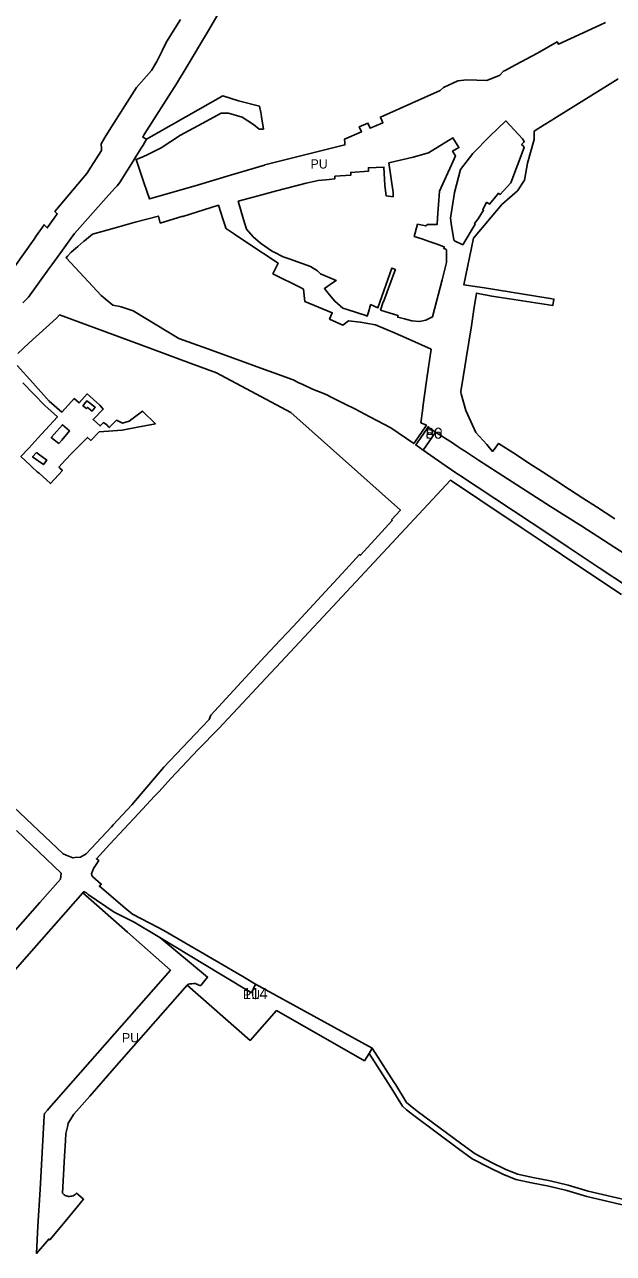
# Model space of a CAD drawing. Extents: x -537034 to -534353, y -1176562 to -1173176.
# Drawn here: x -536157 to -535838, y -1175930 to -1175264 of the extents above; entities that cross this region are included whole.
import ezdxf

# ---------------------------------------------------------------- set-up
doc = ezdxf.new("R2010")
doc.units = 0
for name, color, linetype in [('90320013', 7, 'Continuous'), ('90320023', 7, 'Continuous'), ('90450013', 7, 'Continuous'), ('90450023', 7, 'Continuous'), ('ID_navrh', 7, 'Continuous')]:
    doc.layers.add(name, color=color, linetype=linetype)

msp = doc.modelspace()

# ---------------------------------------------------------------- linework, layer by layer
at = {"layer": '90320013'}
for points in [[(-536006.58, -1175180), (-536057.72, -1175267.69), (-536069.4, -1175287.13), (-536074.57, -1175295.75), (-536092.07, -1175323.29), (-536092.88, -1175324.61), (-536090.76, -1175325.85), (-536092.69, -1175328.97), (-536093.75, -1175330.67), (-536096.43, -1175335), (-536098.11, -1175337.72), (-536104.15, -1175347.45), (-536105.27, -1175349.25), (-536106.82, -1175350.99), (-536107.99, -1175352.3), (-536112.75, -1175357.64), (-536129.84, -1175376.84), (-536131.8, -1175379.55), (-536136.42, -1175385.95), (-536142.22, -1175393.97), (-536143.72, -1175396.05), (-536154.83, -1175411.41), (-536157.86, -1175414.59)], [(-536162.37, -1175394.92), (-536151.81, -1175379.91), (-536150.51, -1175378.06), (-536146.37, -1175372.18), (-536144.69, -1175373.91), (-536144.13, -1175373.13), (-536142.38, -1175370.67), (-536140.9, -1175368.58), (-536139.22, -1175366.23), (-536140.48, -1175364.96), (-536133.87, -1175357.08), (-536125.22, -1175346.76), (-536123.14, -1175344.33), (-536120.96, -1175340.95), (-536115.18, -1175331.96), (-536115.24, -1175330.93), (-536115.4, -1175328.29), (-536113.39, -1175324.91), (-536111.06, -1175320.99), (-536096.32, -1175297.69), (-536088.03, -1175288.6), (-536085.27, -1175283.61), (-536082.34, -1175277.81), (-536079.94, -1175273.05), (-536072.44, -1175260.84)]]:
    msp.add_lwpolyline(points, dxfattribs=at)
at = {"layer": '90320023'}
msp.add_lwpolyline([(-535831.2, -1175903.92), (-535852.06, -1175898.92), (-535862.82, -1175895.79), (-535872.59, -1175893.44), (-535881.94, -1175891.57), (-535890.48, -1175889.76), (-535897.59, -1175886.87), (-535904.65, -1175883.37), (-535914.14, -1175878.49), (-535921.6, -1175873.09), (-535945.82, -1175855.15), (-535949.79, -1175851.94), (-535952.05, -1175849.98), (-535958.16, -1175840.1), (-535958.19, -1175840.06), (-535970.14, -1175821.39), (-535968.39, -1175818.56), (-535956.44, -1175837.23), (-535955.62, -1175838.5), (-535949.74, -1175848.02), (-535947.86, -1175849.64), (-535943.98, -1175852.77), (-535919.82, -1175870.67), (-535912.56, -1175875.93), (-535903.3, -1175880.69), (-535896.35, -1175884.13), (-535889.59, -1175886.88), (-535881.33, -1175888.64), (-535871.94, -1175890.51), (-535862.05, -1175892.89), (-535851.29, -1175896.02), (-535830.38, -1175901.03)], dxfattribs=at)
at = {"layer": '90450013'}
for points in [[(-536157.86, -1175414.59), (-536154.83, -1175411.41), (-536143.72, -1175396.05), (-536142.22, -1175393.97), (-536136.42, -1175385.95), (-536131.8, -1175379.55), (-536129.84, -1175376.84), (-536112.75, -1175357.64), (-536107.99, -1175352.3), (-536106.82, -1175350.99), (-536105.27, -1175349.25), (-536104.15, -1175347.45), (-536098.11, -1175337.72), (-536096.43, -1175335), (-536093.75, -1175330.67), (-536092.69, -1175328.97), (-536090.76, -1175325.85), (-536056.18, -1175306.04), (-536049.5, -1175302.21), (-536040.85, -1175304.92), (-536029.59, -1175307.87), (-536028.73, -1175311.35), (-536028.63, -1175312.06), (-536028.39, -1175313.76), (-536027.63, -1175319.02), (-536027.44, -1175320.35), (-536029.77, -1175320.33), (-536032.73, -1175317.76), (-536038.85, -1175313.85), (-536046.36, -1175311.63), (-536050.36, -1175311.71), (-536060.56, -1175317.19), (-536072.32, -1175323.69), (-536082.9, -1175330.42), (-536089.72, -1175333.91), (-536093.25, -1175335.47), (-536096.47, -1175336.83), (-536092.3, -1175349.19), (-536090.67, -1175354.01), (-536089.26, -1175358.2), (-536075.74, -1175354.33), (-536062.61, -1175350.5), (-536045.32, -1175345.23), (-536026.8, -1175339.78), (-536026.63, -1175339.73), (-535983.2, -1175328.86), (-535983.27, -1175327.65), (-535983.37, -1175325.73), (-535974.27, -1175321.85), (-535975.41, -1175319.17), (-535970.74, -1175317.01), (-535969.56, -1175319.81), (-535962.64, -1175316.84), (-535963.93, -1175313.84), (-535962.27, -1175313.07), (-535931.61, -1175299.47), (-535929.82, -1175297.79), (-535921.95, -1175294.08), (-535917.14, -1175293.69), (-535906.3, -1175294.03), (-535899.54, -1175291.17), (-535899.11, -1175290.99), (-535897.13, -1175288.99), (-535896.37, -1175288.59), (-535890.61, -1175285.56), (-535878.76, -1175279.15), (-535868.04, -1175273.09), (-535867.34, -1175274.28), (-535854.08, -1175268.05), (-535845.03, -1175263.95), (-535841.93, -1175262.54)], [(-535834.99, -1175293.05), (-535839.37, -1175295.79), (-535851.34, -1175303.26), (-535869.92, -1175314.78), (-535870.92, -1175315.4), (-535875.07, -1175317.97), (-535880.62, -1175321.52), (-535880.5, -1175326.03), (-535884.23, -1175338.72), (-535885.84, -1175347.99), (-535889.55, -1175353.76), (-535898.06, -1175361.28), (-535913.48, -1175379.39), (-535918.79, -1175404.67), (-535911.3, -1175405.81), (-535907.6, -1175406.38), (-535871.88, -1175412.1), (-535869.83, -1175412.49), (-535870.37, -1175415.86), (-535893.97, -1175412.4), (-535903.47, -1175410.92), (-535911.79, -1175409.25), (-535913.21, -1175418.12), (-535914.63, -1175427), (-535916.04, -1175435.87), (-535917.46, -1175444.75), (-535918.88, -1175453.63), (-535920.3, -1175462.5), (-535920.4, -1175463.19), (-535920.21, -1175463.87), (-535917.69, -1175472.82), (-535912.13, -1175484.72), (-535906.33, -1175491.38), (-535903.16, -1175495.01), (-535902.34, -1175493.94), (-535899.85, -1175490.69), (-535890.72, -1175496.62), (-535883.39, -1175501.37), (-535876.07, -1175506.12), (-535868.76, -1175510.86), (-535861.43, -1175515.62), (-535854.11, -1175520.37), (-535846.78, -1175525.12), (-535836.82, -1175531.58)], [(-536166.27, -1175684.73), (-536135.96, -1175713.3), (-536134.39, -1175713.94), (-536130.78, -1175715.4), (-536129.64, -1175715.27), (-536126.67, -1175714.93), (-536123.54, -1175713.17), (-536109.87, -1175698.52), (-536108.98, -1175697.57), (-536098.8, -1175686.65), (-536090.64, -1175677.08), (-536089.6, -1175675.86), (-536081.43, -1175666.28), (-536064.41, -1175648.4), (-536056.8, -1175640.41), (-536056.02, -1175638.08), (-536039.26, -1175619.95), (-536026.58, -1175606.23), (-536018.16, -1175597.18), (-536011.37, -1175589.88), (-535982.79, -1175559.15), (-535975.24, -1175550.95), (-535974.85, -1175551.32), (-535957.51, -1175532.51), (-535957.92, -1175532.13), (-535953.14, -1175526.94), (-536012.46, -1175474), (-536052.95, -1175452.48), (-536067.19, -1175447.21), (-536093.87, -1175437.34), (-536137.96, -1175421.02), (-536139.69, -1175422.77), (-536154.62, -1175436.42), (-536160.63, -1175442.04)], [(-536161.02, -1175448.4), (-536152.52, -1175457.9), (-536143.69, -1175467.75), (-536136.82, -1175473.77), (-536131.49, -1175467.97), (-536130.05, -1175466.4), (-536127.41, -1175468.77), (-536122.94, -1175463.84), (-536116.13, -1175469.96), (-536114.25, -1175472.08), (-536119.83, -1175477.7), (-536116.04, -1175481.25), (-536114.16, -1175479.39), (-536112.4, -1175480.71), (-536111.06, -1175482.13), (-536107.55, -1175478.6), (-536107.11, -1175478.16), (-536103.78, -1175479.67), (-536100.16, -1175478.69), (-536093.04, -1175473.16), (-536086.02, -1175480.07), (-536095.7, -1175481.89), (-536104.07, -1175483.46), (-536116.44, -1175484.37), (-536121.1, -1175489.13), (-536122.87, -1175487.43), (-536128.23, -1175492.92), (-536131.48, -1175496.25), (-536134.83, -1175499.68), (-536138.31, -1175503.67), (-536137.84, -1175504.11), (-536136.45, -1175505.41), (-536142.92, -1175512.53), (-536149.09, -1175506.89), (-536150.04, -1175506.03), (-536152.96, -1175503.36), (-536153.95, -1175502.45), (-536158.95, -1175497.88), (-536154.68, -1175493.22), (-536149.75, -1175487.86), (-536145.64, -1175483.38), (-536139.11, -1175476.27), (-536145.9, -1175470.18), (-536157.81, -1175457.83)], [(-535828.09, -1175552.76), (-535854.81, -1175535.62), (-535871.63, -1175524.85), (-535879.25, -1175519.97), (-535910.82, -1175499.75), (-535912.86, -1175498.4), (-535918.33, -1175494.77), (-535919.58, -1175493.94), (-535922.29, -1175492.15), (-535924.91, -1175490.41), (-535934.02, -1175484.62), (-535937.94, -1175482.12), (-535937.87, -1175481.61), (-535940.62, -1175485.52), (-535942.28, -1175487.89), (-535944.84, -1175491.52), (-535940.73, -1175494.38), (-535930.72, -1175501.34), (-535922.97, -1175506.73), (-535922.56, -1175507.02), (-535921.1, -1175507.99), (-535872.67, -1175539.97), (-535862.15, -1175546.92), (-535845.34, -1175558.14), (-535830.04, -1175568.35)], [(-535833.24, -1175572.63), (-535847.63, -1175563), (-535865.17, -1175551.3), (-535875.69, -1175544.28), (-535887.07, -1175536.66), (-535910.06, -1175521.32), (-535924.9, -1175511.41), (-535925.98, -1175510.69), (-535977.32, -1175565.72), (-536020.48, -1175611.98), (-536020.82, -1175612.35), (-536051.58, -1175645.22), (-536062.85, -1175656.58), (-536077.69, -1175672.45), (-536084.04, -1175679.34), (-536086.5, -1175681.99), (-536095.14, -1175691.31), (-536110.68, -1175708), (-536117.97, -1175715.86), (-536116.69, -1175716.89), (-536117.43, -1175717.85), (-536119.59, -1175721.2), (-536120.66, -1175723.99), (-536120.53, -1175724.95), (-536119.96, -1175725.77), (-536115.4, -1175729.64), (-536116.38, -1175730.76), (-536102.6, -1175742.46), (-536098.47, -1175745.97), (-536084.46, -1175753.22), (-536081.42, -1175754.71), (-536047.3, -1175774.7), (-536044.2, -1175776.52), (-536038.6, -1175779.8), (-536031.75, -1175783.82), (-536033.88, -1175788.53), (-536050.74, -1175778.38), (-536083.6, -1175758.57), (-536097.58, -1175750.2), (-536108.31, -1175744.92), (-536122.41, -1175735.27), (-536123.44, -1175734.4), (-536124.31, -1175733.91), (-536124.75, -1175733.67), (-536125.34, -1175734.39), (-536138.55, -1175749.41), (-536151.76, -1175764.43), (-536164.97, -1175779.44)], [(-536161.83, -1175754.68), (-536148.62, -1175739.66), (-536137.41, -1175726.91), (-536137.07, -1175723.72), (-536161.26, -1175700.56)]]:
    msp.add_lwpolyline(points, dxfattribs=at)
for points in [[(-535906.34, -1175359.86), (-535904.88, -1175361.02), (-535901.28, -1175356.77), (-535899.88, -1175355.12), (-535899.09, -1175355.7), (-535897.43, -1175353.97), (-535893.14, -1175349.5), (-535886.06, -1175330.37), (-535886.56, -1175329.45), (-535887.38, -1175328.59), (-535886.24, -1175327.4), (-535885.94, -1175327.08), (-535886.86, -1175325.6), (-535895.9, -1175315.86), (-535904.64, -1175324.13), (-535913.78, -1175333.54), (-535920.54, -1175342.19), (-535923.85, -1175354.67), (-535925.89, -1175368.6), (-535925.38, -1175372.73), (-535924.2, -1175380.17), (-535924.08, -1175380.55), (-535923.75, -1175380.8), (-535919.27, -1175382.97), (-535912.63, -1175371.84), (-535912.86, -1175371.55), (-535911.01, -1175368.92), (-535908.05, -1175364.29), (-535908.49, -1175364)], [(-536033.03, -1175378.74), (-536029.05, -1175382.09), (-536022.5, -1175386.59), (-536021.61, -1175387.05), (-536016.68, -1175389.63), (-536013.48, -1175390.72), (-536001.83, -1175394.83), (-535998.08, -1175397.19), (-535996.48, -1175398.8), (-535987.93, -1175402.35), (-535989.36, -1175403.33), (-535994.33, -1175406.75), (-535992.24, -1175409.31), (-535991.58, -1175410.12), (-535988.7, -1175413.65), (-535984.32, -1175417.42), (-535981.97, -1175418.18), (-535971.92, -1175421.43), (-535971.07, -1175421.71), (-535970.47, -1175419.62), (-535969.54, -1175416.37), (-535969.28, -1175415.49), (-535965.34, -1175417.27), (-535957.76, -1175395.69), (-535955.8, -1175396.5), (-535956.39, -1175397.77), (-535962.34, -1175414.02), (-535962.47, -1175413.98), (-535963.89, -1175418.41), (-535954.48, -1175421.34), (-535954.59, -1175422.36), (-535950.86, -1175423.25), (-535946.91, -1175424.19), (-535942.68, -1175424.63), (-535939.3, -1175423.93), (-535935.67, -1175422.14), (-535930.51, -1175402.01), (-535928.04, -1175392.62), (-535928.17, -1175385.78), (-535928.46, -1175385.39), (-535929.65, -1175384.98), (-535929.35, -1175384.08), (-535933.8, -1175382.49), (-535937.52, -1175381.22), (-535941.5, -1175379.86), (-535945.61, -1175378.45), (-535943.8, -1175371.87), (-535939.34, -1175372.83), (-535938.43, -1175371.97), (-535933.11, -1175371.95), (-535933.01, -1175368.46), (-535931.93, -1175354.02), (-535928.3, -1175345.93), (-535925.36, -1175339.68), (-535923.29, -1175334.88), (-535924.78, -1175332.21), (-535921.41, -1175330.35), (-535924.67, -1175325.13), (-535937.9, -1175333.24), (-535946.12, -1175335.5), (-535959.32, -1175338.64), (-535957.04, -1175354.74), (-535957.09, -1175357), (-535960.79, -1175356.57), (-535961.56, -1175350.82), (-535962.06, -1175340.94), (-535970.46, -1175341.25), (-535970.35, -1175343.05), (-535980.06, -1175343.81), (-535980.04, -1175345.3), (-535988.67, -1175345.91), (-535988.6, -1175347.22), (-535991.84, -1175347.55), (-535997.66, -1175348.18), (-536004.2, -1175349.6), (-536020.27, -1175353.73), (-536032.27, -1175357.01), (-536041.08, -1175359.47), (-536038.15, -1175369.29), (-536038, -1175369.79), (-536036.5, -1175374.59)], [(-535942.12, -1175479.47), (-535941.21, -1175473.05), (-535940.73, -1175469.72), (-535939.08, -1175458.12), (-535938.72, -1175455.59), (-535936.45, -1175439.67), (-535948.57, -1175434.15), (-535957.61, -1175430.28), (-535959.48, -1175429.51), (-535966.6, -1175426.47), (-535974.94, -1175424.92), (-535981.19, -1175424.19), (-535984.27, -1175426.59), (-535991.55, -1175423.3), (-535990.05, -1175419.84), (-536005.01, -1175413.71), (-536005.71, -1175407.02), (-536006.86, -1175406.44), (-536022.26, -1175398.69), (-536019.49, -1175392.92), (-536035.85, -1175382.11), (-536043.14, -1175377.29), (-536048.05, -1175373.99), (-536047.76, -1175373.83), (-536049.18, -1175369.53), (-536051.8, -1175361.59), (-536071.05, -1175367.76), (-536071.2, -1175367.52), (-536083.38, -1175371.29), (-536084.39, -1175367.5), (-536096.96, -1175370.8), (-536108.41, -1175373.94), (-536120.13, -1175377.36), (-536124.4, -1175380.82), (-536124.76, -1175381.12), (-536128.14, -1175384), (-536129.31, -1175385), (-536131.61, -1175387.06), (-536133.72, -1175389.22), (-536134.45, -1175390.08), (-536120, -1175405.62), (-536115.36, -1175410.61), (-536109.05, -1175415.82), (-536105.23, -1175416.52), (-536104.49, -1175416.66), (-536099.12, -1175418.47), (-536098.1, -1175418.81), (-536073.22, -1175433.76), (-536063.19, -1175437.41), (-536060.05, -1175438.56), (-536043.58, -1175444.56), (-536026.8, -1175450.68), (-536021.74, -1175452.52), (-536011.36, -1175456.31), (-536008.13, -1175457.84), (-536006.04, -1175458.83), (-536000.87, -1175461.27), (-535994.28, -1175463.81), (-535992.35, -1175464.77), (-535991.45, -1175465.22), (-535983.02, -1175469.41), (-535977.9, -1175471.95), (-535969.73, -1175476.22), (-535965.56, -1175478.4), (-535958.24, -1175482.22), (-535945.88, -1175490.83), (-535943.35, -1175487.19), (-535941.72, -1175484.84), (-535938.97, -1175480.89)], [(-536125.34, -1175470.36), (-536123.45, -1175471.86), (-536122.9, -1175471.17), (-536120.33, -1175473.23), (-536118.58, -1175471.14), (-536123.17, -1175467.57)], [(-536138.31, -1175490.84), (-536136.78, -1175489.02), (-536132.52, -1175483.97), (-536136.34, -1175480.56), (-536140.83, -1175485.66), (-536142.49, -1175487.54)], [(-536150.52, -1175495.56), (-536152.65, -1175498.03), (-536150.92, -1175499.24), (-536149.6, -1175500.17), (-536146.73, -1175502.18), (-536144.96, -1175499.79), (-536147.58, -1175497.8), (-536148.85, -1175496.83)], [(-536068.68, -1175784.44), (-536081.89, -1175799.46), (-536095.1, -1175814.47), (-536108.31, -1175829.49), (-536121.52, -1175844.51), (-536130.22, -1175854.41), (-536133.25, -1175859.28), (-536133.54, -1175860.57), (-536134.52, -1175864.88), (-536134.74, -1175868.81), (-536135.21, -1175877.09), (-536136.35, -1175897.22), (-536135.92, -1175897.66), (-536135.43, -1175898.05), (-536134.9, -1175898.37), (-536134.33, -1175898.63), (-536133.73, -1175898.81), (-536133.12, -1175898.91), (-536132.5, -1175898.94), (-536131.88, -1175898.89), (-536131.27, -1175898.76), (-536130.68, -1175898.56), (-536130.12, -1175898.29), (-536129.6, -1175897.95), (-536129.13, -1175897.55), (-536128.71, -1175897.09), (-536125.16, -1175900.27), (-536124.92, -1175900.48), (-536134.11, -1175911.51), (-536143.3, -1175922.54), (-536143.86, -1175922.07), (-536150.53, -1175929.84), (-536149.69, -1175915.07), (-536148.56, -1175895.1), (-536147.42, -1175875.13), (-536146.29, -1175855.17), (-536146.22, -1175853.97), (-536144.59, -1175852.11), (-536143.87, -1175851.28), (-536130.66, -1175836.27), (-536117.45, -1175821.25), (-536104.24, -1175806.23), (-536091.03, -1175791.21), (-536077.82, -1175776.2), (-536101.05, -1175755.76), (-536125.34, -1175734.39), (-536124.75, -1175733.67), (-536124.31, -1175733.91), (-536123.44, -1175734.4), (-536122.41, -1175735.27), (-536108.31, -1175744.92), (-536097.58, -1175750.2), (-536083.6, -1175758.57), (-536057.71, -1175780.04), (-536061.37, -1175784.57), (-536061.87, -1175784.56), (-536062.74, -1175784.22), (-536063.6, -1175783.87), (-536064.47, -1175783.53), (-536065.23, -1175783.56), (-536066.29, -1175783.62), (-536067.19, -1175783.66), (-536067.99, -1175783.9)]]:
    msp.add_lwpolyline(points, close=True, dxfattribs=at)
at = {"layer": '90450023'}
for points in [[(-535940.73, -1175494.38), (-535944.84, -1175491.52), (-535942.28, -1175487.89), (-535940.62, -1175485.52), (-535937.87, -1175481.61), (-535937.94, -1175482.12), (-535934.02, -1175484.62), (-535934.25, -1175484.93)], [(-536031.75, -1175783.82), (-535968.39, -1175818.56), (-535970.14, -1175821.39), (-535972.61, -1175825.36), (-536020.26, -1175798.17), (-536034.67, -1175814.36), (-536068.68, -1175784.44), (-536067.99, -1175783.9), (-536067.19, -1175783.66), (-536066.29, -1175783.62), (-536065.23, -1175783.56), (-536064.47, -1175783.53), (-536063.6, -1175783.87), (-536062.74, -1175784.22), (-536061.87, -1175784.56), (-536061.37, -1175784.57), (-536057.71, -1175780.04), (-536083.6, -1175758.57), (-536050.74, -1175778.38), (-536033.88, -1175788.53)]]:
    msp.add_lwpolyline(points, close=True, dxfattribs=at)

# ---------------------------------------------------------------- texts
at = {"layer": '90450013'}
for p in [(-536001.85, -1175341.68), (-536104.12, -1175815.41)]:
    msp.add_text('PU', height=5, rotation=360, dxfattribs=at).set_placement(p)
at = {"layer": '90450023'}
for p in [(-535939.43, -1175488.16), (-536038.51, -1175791.96)]:
    msp.add_text('PU', height=5, rotation=360, dxfattribs=at).set_placement(p)
at = {"layer": 'ID_navrh'}
for s, rotation, p in [('86', 360, (-535939.43, -1175488.16)), ('114', 0, (-536038.51, -1175791.96))]:
    msp.add_text(s, height=6, rotation=rotation, dxfattribs=at).set_placement(p)

doc.saveas('drawing.dxf')
